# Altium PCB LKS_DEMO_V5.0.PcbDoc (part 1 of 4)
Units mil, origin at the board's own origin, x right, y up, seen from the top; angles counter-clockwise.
Board outline 5414.8 x 3354.56 mil, 2 copper layers (Top Layer, Bottom Layer); 131 components, 85 nets, 355 pads, 272 vias.
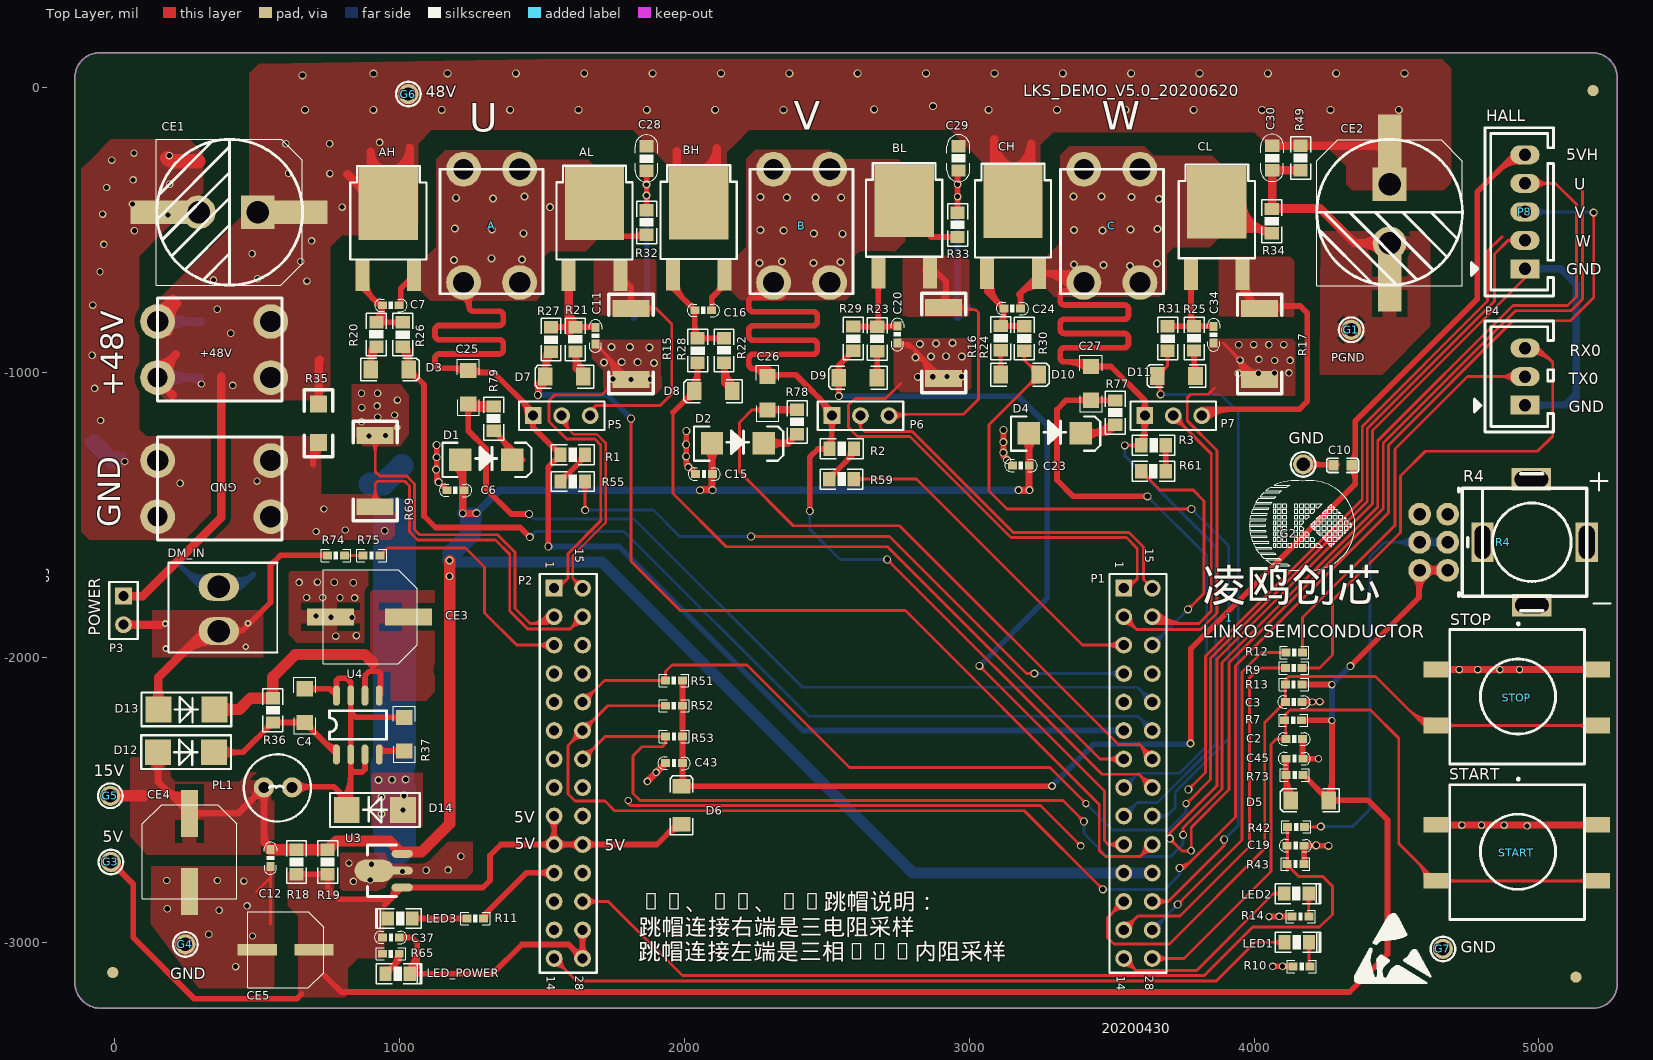
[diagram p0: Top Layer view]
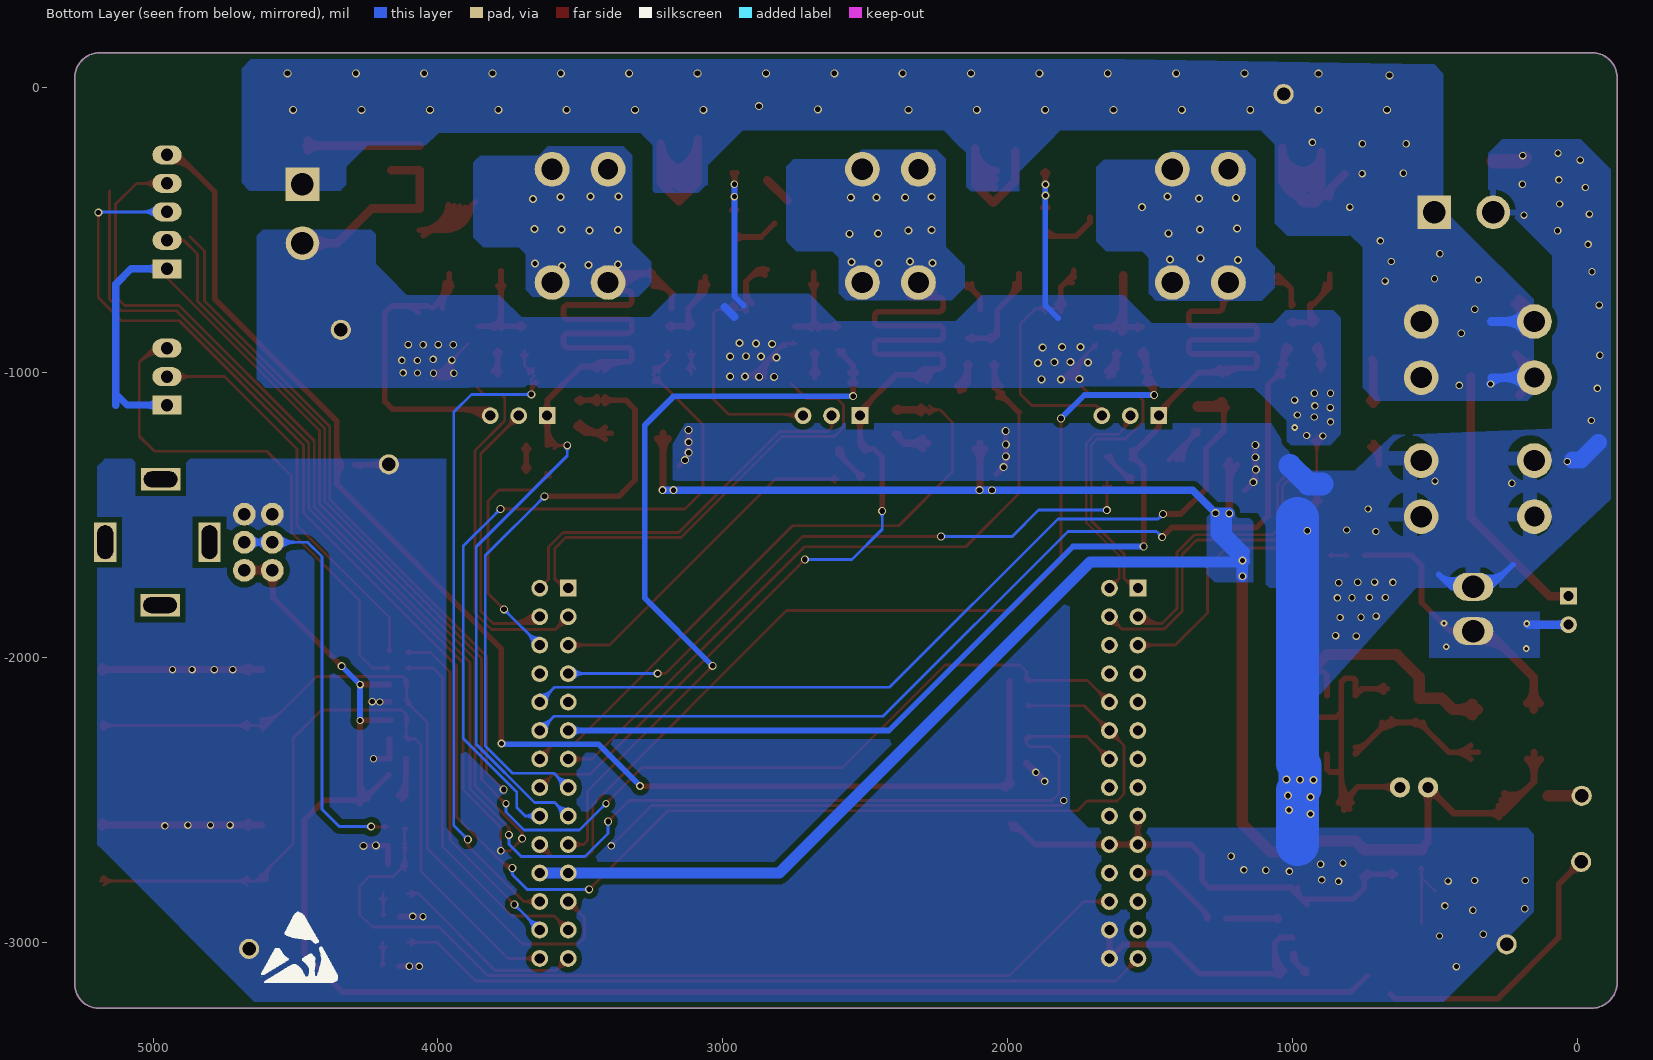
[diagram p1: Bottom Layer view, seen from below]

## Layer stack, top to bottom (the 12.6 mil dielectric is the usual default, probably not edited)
Top Layer: signal copper 1.4
Dielectric: dielectric 12.6, FR-4, Dk 4.8
Bottom Layer: signal copper 1.4

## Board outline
-140.37,-3140.27 ccw(c-48.64,-3140.27) -48.64,-3232 5190.27,-3231.65 ccw(c5190.27,-3147.49) 5274.43,-3147.49 5274.43,35.95 ccw(c5187.82,35.95) 5187.82,122.56 -53.53,122.56 ccw(c-53.53,35.95) -140.14,35.95

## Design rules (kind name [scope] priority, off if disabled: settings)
Clearance [InPolygon] p1: gap=20
Clearance Clearance_48V [InNet('+48V')] p2: gap=30
Clearance Clearance_4 [InNet('PGND')] p3 off: gap=20
Clearance Clearance_5V [InNet('+5V')] p4 off: gap=20
Clearance Clearance_15V [InNet('+15V')] p5: gap=20
Clearance Clearance_5 [All] p6: gap=7.87
ComponentClearance [All] p1 off: gap=0 collisioncheckmode=3 verticalgap=0 showdistances=FALSE
FabricationTestpoint [(IsPad And (OnTopLayer Or OnBottomLayer))] p1: side=3 testpointundercomponent=TRUE minsize=40 maxsize=100 preferedsize=60 minholesize=0 maxholesize=40 preferedholesize=32 testpointgrid=1 allowsidetop=TRUE allowsidebottom=TRUE usegrid=TRUE gridtolerance=0.01
PlaneConnect [All] p1: planeconnectstyle=Direct reliefexpansion=20 reliefentries=4 reliefconductorwidth=10 reliefairgap=10
PolygonConnect [All] p1: connectstyle=Direct reliefconductorwidth=50 reliefentries=4 polygonreliefangle="90 Angle"
RoutingVias [All] p1: holewidth=13.78 width=19.68 viastyle="Through Hole" minholewidth=13.78 minwidth=19.68 maxholewidth=13.78 maxwidth=19.68
SilkscreenOverComponentPads SilkToSolderMaskClearance [IsPad] p1: minsilkscreentomaskgap=10
SolderMaskExpansion [All] p1: expansion=4
Width Width_2 [All] p1 off: maxlimit=10 minlimit=10 preferedwidth=10
Width Width_1 [InNet('5V-T')] p2 off: maxlimit=40 minlimit=40 preferedwidth=40
Width Width_VH [InNet('5V1')] p3 off: maxlimit=40 minlimit=40 preferedwidth=40
Width Width_5V [InNet('5V')] p4 off: maxlimit=40 minlimit=40 preferedwidth=40
Width Width_14.3V [InNet('+14.3V')] p5 off: maxlimit=50 minlimit=50 preferedwidth=50
Width Width_15V [InNet('+15V')] p6 off: maxlimit=40 minlimit=40 preferedwidth=40
Width Width_48V [InNet('+48V')] p7 off: maxlimit=40 minlimit=40 preferedwidth=40
Width [All] p8: maxlimit=200 minlimit=1 preferedwidth=40
24 further rules are at their usual default settings.

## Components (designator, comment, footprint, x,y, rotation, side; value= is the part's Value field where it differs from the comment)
1 "LKS_sign" LKS_LOGO2 3913.31,-1861.12 r0 top
+48V "M4" M4_CONECTOR 587.24,-737.97 r180 top
A "M4" M4_CONECTOR 1503.84,-723.16 r90 top
AH "NCE8295AK" TO-252 960.46,-532.18 r0 top
AL "NCE8295AK" TO-252 1684.09,-531.73 r0 top
B "M4" M4_CONECTOR 2592.15,-723.16 r90 top
BH "NCE8295AK" TO-252 2050.06,-530.17 r0 top
BL "NCE8295AK" TO-252 2771.14,-522.9 r0 top
C "M4" M4_CONECTOR 3681.8,-723.16 r90 top
C2 "100nF/50V" 0603C#1 4170.04,-2286.71 r180 top
C3 "100nF/50V" 0603C#1 4109.35,-2156.04 r0 top
C4 "10uF/100V" 1206#1 666.13,-2227.86 r90 top (schematic designator CF2)
C6 "100nF/50V" 0603C#1 1166.15,-1413.01 r0 top
C7 "10nF/50V" 0603C#1 939.25,-763.4 r0 top
C10 "100nF/50V" 0603C#2 4310.55,-1325.62 r180 top
C11 "10nF/50V" 0603C#1 1687.64,-841.38 r270 top
C12 "100nF/50V" 0603C#1 546.38,-2675.06 r270 top (schematic designator C351)
C15 "100nF/50V" 0603C#1 2039.42,-1355.82 r0 top
C16 "10nF/50V" 0603C#1 2036.35,-781.02 r0 top
C19 "100nF/50V" 0603C#1 4174.8,-2661.32 r180 top
C20 "10nF/50V" 0603C#1 2747.52,-836.3 r270 top
C23 "100nF/50V" 0603C#1 3151.34,-1325.92 r0 top
C24 "10nF/50V" 0603C#1 3121.14,-774.76 r0 top
C25 "10uF/25V" 1206#1 1240.4,-1110.36 r90 top (schematic designator CAH1)
C26 "10uF/25V" 1206#1 2291.34,-1131.27 r90 top (schematic designator CBH1)
C27 "10uF/25V" 1206#1 3426.66,-1096.7 r90 top (schematic designator CCH1)
C28 "100nF/100V" 0805C 1866.99,-290.99 r90 top (schematic designator CA)
C29 "100nF/100V" 0805C 2961.99,-290.67 r90 top (schematic designator CB)
C30 "100nF/100V" 0805C 4063.55,-289.6 r90 top (schematic designator CC)
C34 "10nF/50V" 0603C#1 3857.8,-837.72 r270 top
C37 "100nF/50V" 0603C#1 998.61,-2983.24 r180 top
C43 "100nF/50V" 0603C#1 1933.69,-2371.26 r0 top
C45 "100nF/50V" 0603C#1 4170.76,-2355.72 r180 top
CE1 "220uF/63V" "220UF/25V 12.5*12.5" 503.17,-437.15 r270 top (schematic designator CC3)
CE2 "220uF/63V" "220UF/25V 12.5*12.5" 4475.37,-337.23 r0 top (schematic designator CC1)
CE3 "10UF/100V" "220UF/25V paster8*10" 894.06,-1857.56 r270 top (schematic designator CF1)
CE4 "220uF/25V  8*10" "220UF/25V paster8*10" 262.36,-2684.79 r0 top (schematic designator C391)
CE5 "220uF/16V" "220UF/16V PASTER6.3*7.7 - DUPLICATE" 599.7,-3026.55 r270 top (schematic designator C36)
CH "NCE8295AK" TO-252 3153.33,-524.74 r0 top
CL "NCE8295AK" TO-252 3869.04,-527.35 r0 top
D1 "US1J" SMA金丰 1304.37,-1305.74 r0 top
D2 "US1J" SMA金丰 2187.53,-1248.27 r0 top
D3 "1N4007" D1206#1 898.55,-988.88 r0 top
D4 "US1J" SMA金丰 3300.41,-1213.21 r0 top
D5 "1N4007" D1206#2 4130.39,-2500.13 r0 top
D6 "1N4007" D1206#2 1990.99,-2454.23 r270 top
D7 "1N4007" D1206#1 1645.15,-1014.31 r180 top
D8 "1N4007" D1206#1 2167.67,-1065.43 r180 top
D9 "1N4007" D1206#1 2675.86,-1018.22 r180 top
D10 "1N4007" D1206#1 3110.43,-1007.51 r0 top
D11 "1N4007" D1206#1 3793.99,-1012.14 r180 top
D12 "ES1J" DO-214AC 250.05,-2333.06 r0 top (schematic designator DP1)
D13 "1N4007" DO-214AC 251.5,-2182.97 r0 top (schematic designator DD6)
D14 "ES1J" DO-214AC 912.83,-2535.22 r180 top (schematic designator D02)
DM_IN "CON2" SIP3.96-2 365.35,-1907.97 r90 top
G1 "PAD1.2" PAD1.2 4340.63,-849.76 r0 top
G2 "PAD1.2" PAD1.2 4171.95,-1322.36 r0 top
G3 "PAD1.2" PAD1.2 -13.75,-2718.17 r0 top
G4 "PAD1.2" PAD1.2 247.83,-3007.54 r0 top
G5 "PAD1.2" PAD1.2 -15.81,-2485.75 r0 top
G6 "PAD1.2" PAD1.2 1030.82,-22.05 r0 top (schematic designator G12)
G7 "PAD1.2" PAD1.2 4662.85,-3023.47 r0 top
GND "M4" M4_CONECTOR 587.24,-1226.14 r180 top
LED1 "LED" SOD323 4146.77,-2998.22 r0 top
LED2 "LED" SOD323 4145.98,-2827.12 r0 top
LED3 "LED" SOD323 1003.88,-2918.56 r180 top
LED_POWER "LED_R" SOD323 990.38,-3108.82 r0 top (schematic designator LED)
P1 "Header 14X2A" HDR2X14_CEN 3542.25,-1756.82 r270 top (schematic designator P7)
P2 "Header 14X2A" HDR2X14_CEN 1542.25,-1756.82 r270 top (schematic designator P5)
P3 "Header 2" HDR1X2 30.28,-1784.94 r270 top
P4 "P13" 2.54-XH-3A-180 4950.98,-1114.16 r270 top (schematic designator P13)
P5 "Header 3" HDR1X3 1468.79,-1151.24 r0 top (schematic designator P17)
P6 "Header 3" HDR1X3 2517.75,-1151.24 r0 top (schematic designator P18)
P7 "Header 3" HDR1X3 3616.05,-1151.24 r0 top (schematic designator P19)
P8 "Header 5" 2.54-XH-5A-180 4950.7,-435.64 r270 top (schematic designator P21)
PL1 "330uH" L_DIP_6*8MM 523.71,-2456.42 r0 top
R1 "20K 1%" 0805R 1650.48,-1288.54 r180 top
R2 "20K 1%" 0805R 2594.94,-1267.81 r180 top
R3 "20K 1%" 0805R 3689.51,-1255.52 r180 top
R4 "RPot" RK097-W-1 4874.36,-1595.66 r270 top
R7 "10K" 0603R 4166.32,-2220.83 r180 top
R9 "10R" 0603R 4109.61,-2037.33 r0 top
R10 "1K1%" 0603R 4195.91,-3084.6 r180 top
R11 "1K1%" 0603R 1236.12,-2916.6 r0 top (schematic designator R27)
R12 "10R" 0603R 4170.04,-1982.47 r180 top
R13 "10K" 0603R 4109.35,-2095.34 r0 top
R14 "1K1%" 0603R 4192,-2909.82 r180 top
R15 "0.005R/2512" 2512 1812.75,-776.09 r270 top (schematic designator R301)
R16 "0.005R/2512" 2512 2909.76,-1019.43 r90 top (schematic designator R302)
R17 "0.005R/2512" 2512 4019.41,-776.09 r270 top (schematic designator R303)
R18 "1.5K" 0805R 637.92,-2675.77 r270 top (schematic designator R791)
R19 "1.5K" 0805R 747.07,-2675.77 r270 top (schematic designator R761)
R20 "10R" 0805R 918.27,-823.64 r270 top (schematic designator K+A1)
R21 "10R" 0805R 1616.94,-840.56 r270 top (schematic designator K-A1)
R22 "10R" 0805R 2138.61,-879.87 r270 top (schematic designator K+B1)
R23 "10R" 0805R 2676.33,-839.51 r270 top (schematic designator K-B1)
R24 "10R" 0805R 3110.16,-836.37 r270 top (schematic designator K+C1)
R25 "10R" 0805R 3789.15,-837.14 r270 top (schematic designator K-C1)
R26 "51R" 0805R 1010.51,-909.43 r90 top (schematic designator K1)
R27 "51R" 0805R 1531.29,-926.62 r90 top (schematic designator K2)
R28 "51R" 0805R 2046.11,-965.39 r90 top (schematic designator K3)
R29 "51R" 0805R 2592.71,-923.58 r90 top (schematic designator K4)
R30 "51R" 0805R 3192.94,-922.91 r90 top (schematic designator K5)
R31 "51R" 0805R 3696.16,-923.03 r90 top (schematic designator K6)
R32 "51K" 0805R 1866.99,-429.93 r270 top (schematic designator RA1)
R33 "51K" 0805R 2958.78,-438.57 r270 top (schematic designator RB1)
R34 "51K" 0805R 4061.82,-425.61 r270 top (schematic designator RC1)
R35 "47K/0805" 1206#2 715.63,-1177.64 r270 top (schematic designator RA-5)
R36 "150K" 0805R 554.9,-2228.54 r90 top (schematic designator RP1)
R37 "1R" 1206#1 1016.08,-2328.28 r90 top (schematic designator RP2)
R42 "10K" 0603R 4176.57,-2594.78 r180 top
R43 "20K1%" 0603R 4174.28,-2725.73 r180 top
R49 "51K" 0805R 4162.89,-204.18 r270 top
R51 "2K" 0603R 1933.22,-2081.37 r0 top
R52 "2K" 0603R 1933.48,-2169.52 r0 top
R53 "2K" 0603R 1933.69,-2278.19 r0 top
R55 "20K 1%" 0805R 1650.48,-1382.3 r180 top
R59 "20K 1%" 0805R 2594.28,-1374.16 r180 top
R61 "20K 1%" 0805R 3603.91,-1346.42 r0 top
R65 "3.3K" 0603R 939.57,-3040.48 r0 top
R69 "0.005R/2512" 2512 914.66,-1222.47 r270 top
R73 "10K" 0603R 4171.21,-2412.65 r180 top
R74 "20K1%" 0603R 746.62,-1641.8 r0 top
R75 "20K1%" 0603R 871.84,-1641.8 r0 top
R77 "4.7R" 0805R 3512.15,-1097.85 r270 top
R78 "4.7R" 0805R 2395.27,-1130.53 r270 top
R79 "4.7R" 0805r 1329.96,-1118.93 r270 top
START "SW-PB" "SW-PB  12*12" 4922.12,-2685.6 r0 top
STOP "SW-PB" "SW-PB  12*12" 4922.12,-2140.75 r0 top
U3 "LM7805" SOT-89 959.68,-2748.61 r90 top
U4 "LKS611" so-8 780.21,-2340.28 r90 top

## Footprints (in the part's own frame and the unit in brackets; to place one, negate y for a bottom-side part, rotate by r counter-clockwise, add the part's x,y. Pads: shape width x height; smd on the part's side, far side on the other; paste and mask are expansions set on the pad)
2.54-XH-3A-180 [mm]
  rect 1.7x2.6 hole 1.1: 1(0,0)
  oval 1.7x2.6 hole 1.1: 2(-2.54,0) 3(-5.08,0)
  silkscreen extent -7.49,-4.5 2.41,2.54
2.54-XH-5A-180 [mm]
  rect 1.7x2.6 hole 1.1: 1(5.08,0)
  oval 1.7x2.6 hole 1.1: 2(2.54,0) 3(0,0) 4(-2.54,0) 5(-5.08,0)
  silkscreen extent -7.49,-4.78 7.49,2.54
"220UF/16V PASTER6.3*7.7 - DUPLICATE" [mm]
  rect 1x3.5 smd: 1(0,2.54) 2(0,-2.54)
  silkscreen extent -3.4,-3.4 3.4,3.4
"220UF/25V 12.5*12.5" [mm]
  rect 2.1x5.5 smd: 1(0,3.429)
  rect 3x3 hole 2: 1(0,-0.04)
  round 3 hole 2: 2(0,-5.3)
  rect 2.1x5 smd: 2(0,-8.867)
  silkscreen extent -6.5,-9.07 6.5,3.96
"220UF/25V paster8*10" [mm]
  rect 1.5x4.2 smd: 1(0,3.492) 2(0,-3.492)
  silkscreen extent -4.2,-4.13 4.2,4.27
0603C#1 [mm]
  rect 0.8x0.7 smd: 1(0,0) 2(1.5,0)
  silkscreen extent -0.68,-0.57 2.21,0.55
0603C#2 [mm]
  rect 0.9x0.95 smd: 1(-0.813,0) 2(0.813,0)
  silkscreen extent -1.42,-0.64 1.42,0.64
0603R [mm]
  rect 0.8x0.7 smd: 1(0,0) 2(1.5,0)
  silkscreen extent -0.55,-0.55 2.05,0.55
0805C [mm]
  rect 1.1x1.27 smd: 1(0,0) 2(2.175,0)
  silkscreen extent -1,-1.01 3.2,1.03
0805R [mm]
  rect 1.1x1.27 smd: 1(0,0) 2(2.175,0)
  silkscreen extent -0.81,-0.89 3,0.89
0805r [mm]
  rect 1.1x1.27 smd: 1(0,0) 2(2.175,0)
  silkscreen extent -0.81,-0.89 3,0.89
1206#1 [mm]
  rect 1.35x1.45 smd: 1(-0.01,-0.01) 2(2.99,-0.01)
  silkscreen extent -1.02,-1 4,0.98
1206#2 [mm]
  rect 1.524x1.524 smd: 1(-1.714,0) 2(1.714,0)
  silkscreen extent -2.98,-1.27 2.98,1.27
2512 [mm]
  rect 1.5x3.3 smd: 1(-0.04,-0.01) 2(6.31,-0.01)
  silkscreen extent -1.31,-1.98 7.56,1.96
D1206#1 [mm]
  rect 1.3x1.6 smd: 1(0,0) 2(3.4,0)
  silkscreen extent -0.91,-1.02 4.31,1.02
D1206#2 [mm]
  rect 1.3x1.6 smd: 1(3.346,-0.04) 2(-0.054,-0.04)
  silkscreen extent -0.97,-1.06 4.26,0.98
DO-214AC [mm]
  rect 2.3x2.3 smd: 1(-2.502,0) 2(2.502,0)
  silkscreen extent -4,-1.5 4,1.52
HDR1X2 [mm] "Connector; Header; 2 Position"
  rect 1.5x1.5 hole 0.9: 1(0,0)
  round 1.5 hole 0.9: 2(2.54,0)
  silkscreen extent -1.27,-1.27 3.81,1.27
HDR1X3 [mm]
  rect 1.5x1.5 hole 0.9: 1(0,0)
  round 1.5 hole 0.9: 2(2.54,0) 3(5.08,0)
  silkscreen extent -1.27,-1.27 6.35,1.27
HDR2X14_CEN [mm] "Connector; Header; 14x2 Position"
  rect 1.5x1.5 hole 0.9: 1(0,0)
  round 1.5 hole 0.9: 2(2.54,0) 3(5.08,0) 4(7.62,0) 5(10.16,0) 6(12.7,0) 7(15.24,0) 8(17.78,0) 9(20.32,0) 10(22.86,0) 11(25.4,0) 12(27.94,0) 13(30.48,0) 14(33.02,0) 15(0,2.54) 16(2.54,2.54) 17(5.08,2.54) 18(7.62,2.54) 19(10.16,2.54) 20(12.7,2.54) 21(15.24,2.54) 22(17.78,2.54) 23(20.32,2.54) 24(22.86,2.54) 25(25.4,2.54) 26(27.94,2.54) 27(30.48,2.54) 28(33.02,2.54)
  silkscreen extent -1.27,-1.27 34.29,3.81
L_DIP_6*8MM [mm]
  round 1.8 hole 1: 1(0,0) 2(2.5,0)
  silkscreen extent -1.8,-3.04 4.2,2.96
LKS_LOGO2 [mil]
  silkscreen extent 70,167 440,482
M4_CONECTOR [mm]
  round 3.1 hole 1.9: 1(1,7.1) 1(1,2.1) 1(11.1,2.1)
  round 3.1 hole 1.8: 1(11.1,7.1)
  silkscreen extent 0,0 11.1,9.2
PAD1.2 [mm]
  round 1.8 hole 1.2: 1(0,0)
  silkscreen extent -1.1,-1.1 1.1,1.1
RK097-W-1 [mm] "电位器-"
  rect 2x3.5 hole 1.4 slot 3 at 90 deg: 0(-5.613,2.503) 0(5.613,2.554)
  rect 3.5x2 hole 1.4 slot 3 at 0 deg: 0(0,7.45) 0(0,-1.85)
  round 2.032 hole 1.1: 1(2.5,-7.45) 2(-2.5,-7.45) 3(0,-7.45) 4(-2.5,-4.95) 5(0,-4.95) 6(2.5,-4.95)
  silkscreen extent -6.1,-3.95 6.1,7.45
SIP3.96-2 [mm]
  oval 2.5x3.6 hole 2: 1(0,0) 2(3.96,0)
  silkscreen extent -1.91,-5.21 6.1,4.5
SMA金丰 [mm]
  rect 2x2 smd: 1(-2.312,0) 2(2.313,0)
  silkscreen extent -3.91,-1.55 4.04,1.5
so-8 [mm]
  oval 1.8x0.61 smd: 1(-0.02,0.05) 2(-0.02,-1.22) 3(-0.02,-2.49) 4(-0.02,-3.76) 5(5.238,-3.76) 6(5.238,-2.49) 7(5.238,-1.22) 8(5.238,0.05)
  silkscreen extent 1.35,-4.4 3.89,0.68
SOD323 [mil]
  rect 43.31x50 smd: 1(-40,-2) 2(45.63,-2)
  silkscreen extent -72,-37 87,33
SOT-89 [mm]
  oval 0.7x1.9 smd: 1(-1.5,-1.25) 3(1.5,-1.25)
  oval 2x3.5 smd: 2(0,1.25)
  oval 0.7x2.1 smd: 2(0,-1.15)
  silkscreen extent -2.3,-0.75 2.3,1.85
"SW-PB  12*12" [mm]
  rect 2.2x1.397 smd: 1(-7.2,2.5) 2(-7.2,-2.5) 3(7.2,2.5) 4(7.2,-2.5)
  silkscreen extent -5.98,-5.94 6.02,6.68
TO-252 [mm]
  rect 1.25x2.85 smd: 1(-2.3,-3.2) 3(2.3,-3.2)
  rect 5.3x6.5 smd: 2(0,3.2)
  silkscreen extent -3.4,-1.8 3.4,6.55

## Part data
A B C: library part Socket, "Socket"
C4: library part Cap, "Capacitor"
CE1 CE3: library part CD, "Electrolytic Capacitor"
CE2: library part "Cap Pol1", "Polarized Capacitor (Radial)"
D3 D7 D8 D9 D10 D11: library part Diode, "Default Diode"
D5 D6: library part "Diode 1N4007", "1 Amp General Purpose Rectifier"
D12 D13 D14: library part D, "Diode"
DM_IN: "Connector"
G1 G2 G3 G4 G5 G6 G7: library part CON1, "Connector"
LED_POWER: library part LED
P1: "Header, 14-Pin, Dual row"
P3: "Header, 2-Pin"
P8: "Header, 5-Pin"
PL1: library part L
R1 R2 R3: library part RES/1
R4: "Potentiometer"
R11 R36 R37: library part Res2, "Resistor"
R18 R19: library part R-2W, "1W或2W?"
R20 R21 R22 R23 R24 R25 R26 R27 R28 R29 R30 R31: library part Res1, "Resistor"
R35 R42 R43 R74 R75: library part R
R69: library part RES2?
R79: library part RES2短
START STOP: "Switch"

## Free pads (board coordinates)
  round 39.37 / inner round 0 / far side round 0 all layers, no hole: 1(-7.22,-3106.07) 3(5189.97,-9.89) 4(5129.69,-3122.48)

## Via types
v1: diameter 26, hole 18, Top Layer to Bottom Layer, 117 vias
v2: diameter 28, hole 20, Top Layer to Bottom Layer, 77 vias
v3: diameter 28, hole 18, Top Layer to Bottom Layer, 73 vias
v4: diameter 23.62, hole 11.81, Top Layer to Bottom Layer, 5 vias

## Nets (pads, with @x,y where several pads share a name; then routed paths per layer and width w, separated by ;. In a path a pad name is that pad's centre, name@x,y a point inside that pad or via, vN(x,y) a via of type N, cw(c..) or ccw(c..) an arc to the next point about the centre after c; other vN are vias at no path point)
5V-T: C45.2 D5.2 R73.2 | length 344.8
  Top Layer w20: R73.2@4111.7,-2412.19 C45.2@4111.7,-2355.72 ; D5.2@4112.15,-2485.74 R73.2@4112.15,-2412.65 ; 4112.15,-2467.56 ccw(c4156.51,-2467.56) 4125.15,-2498.92 cw(c4156.51,-2467.56) 4112.15,-2467.56 ; R73.2@4112.15,-2419.27 ccw(c4204.79,-2419.27) 4139.29,-2484.78 cw(c4204.79,-2419.27) R73.2@4112.15,-2419.27
5VH: C10.1 C43.2 D6.2 P8.5 R51.2 R52.2 R53.2 | length 5492.9
  Top Layer w20: D6.2@1989.42,-2452.1 v3@3289.67,-2452.1 ; R52.2@1992.54,-2169.52 R52.2@1992.75,-2169.52 ; D6.2@1992.75,-2448.77 R51.2@1992.75,-2081.84 ; v3@3777.74,-2302.94 3777.74,-1968.54 4354.39,-1391.89 4354.39,-1170.91 4782.69,-742.6 4782.69,-366.17 4913.23,-235.64 P8.5@4950.7,-235.64 ; D6.2@2006.35,-2441.08 ccw(c2032.96,-2414.46) 2032.96,-2452.1 ; D6.2@2006.35,-2441.08 cw(c2039.18,-2408.25) 1992.75,-2408.25 ccw(c2039.18,-2408.25) D6.2@2006.35,-2441.08 ; D6.2@2006.35,-2441.08 ccw(c2032.96,-2414.46) 2032.96,-2452.1 ; 2032.96,-2452.1 ccw(c2032.96,-2489.74) 2006.35,-2463.13 cw(c2032.96,-2489.74) 2032.96,-2452.1 ; D6.2@1984.3,-2441.08 ccw(c1963.9,-2420.68) 1992.75,-2420.68 cw(c1963.9,-2420.68) D6.2@1984.3,-2441.08 ; C10.1@4337.09,-1332.06 cw(c4295.34,-1373.81) 4354.39,-1373.81 ccw(c4295.34,-1373.81) C10.1@4337.09,-1332.06 ; C10.1@4337.09,-1319.18 ccw(c4295.34,-1277.43) 4354.39,-1277.43 cw(c4295.34,-1277.43) C10.1@4337.09,-1319.18 ; 4859.2,-289.66 cw(c4932.98,-363.44) 4932.98,-259.1 ccw(c4932.98,-363.44) 4859.2,-289.66 ; 4893.34,-255.52 cw(c4932.98,-295.16) 4932.98,-239.1 ccw(c4932.98,-295.16) 4893.34,-255.52
  Bottom Layer w20: v3(3289.67,-2451.14) 3435.89,-2304.92 3774.41,-2304.92 v3(3776.77,-2302.56) ; 3761.41,-2304.92 ccw(c3761.41,-2287.2) 3773.94,-2299.73 cw(c3761.41,-2287.2) 3761.41,-2304.92
+5V: C37.2 CE5.1 D5.1 D6.1 G3.1 LED3.2 P2.9 P2.10 P2.24 R4.1 R4.6 R7.1 R13.2 R18.2 R19.2 R65.1 R73.1 U3.1 | length 11175.9
  Top Layer w20: G3.1@-13.75,-2718.17 64.46,-2796.38 64.46,-2983.74 279.1,-3198.38 639.24,-3198.38 655.62,-3181.99 ; R18.2@637.92,-2761.01 747.07,-2761.01 747.07,-2809.07 787,-2849 967.55,-2849 ; 738.26,-3117.97 794.75,-3174.47 4335.11,-3174.47 4467.98,-3041.6 4467.98,-2569.96 4399.74,-2501.71 D5.1@4262.12,-2501.71 ; 947.87,-2868.69 U3.1@1008.89,-2807.66 1292.23,-2807.66 1317,-2782.89 1317,-2695.27 1355.46,-2656.82 P2.10@1542.25,-2656.82 ; P2.9@1542.25,-2556.82 P2.10@1542.25,-2656.82 ; D6.1@1989.42,-2585.96 1973.94,-2585.96 1903.08,-2656.82 P2.24@1642.25,-2656.82 P2.10@1542.25,-2656.82 ; R7.1@4166.32,-2220.83 v1@4272.99,-2220.83 ; R13.2@4168.4,-2095.34 v1(4273,-2095.35) ; R73.1@4171.21,-2412.65 4172.92,-2412.65 D5.1@4262.02,-2501.75 ; D5.1@4272.99,-2490.84 v1(4272.99,-2221.42) ; v2(4337.69,-2030.68) 4578.6,-1789.77 4578.6,-1692.52 R4.6@4677.02,-1692.52 ; 29.67,-2761.58 ccw(c-13.75,-2805) -13.75,-2743.6 cw(c-13.75,-2805) 29.67,-2761.58 ; 29.67,-2761.58 cw(c73.08,-2718.17) 11.68,-2718.17 ccw(c73.08,-2718.17) 29.67,-2761.58 ; 747.07,-2789.53 ccw(c718.94,-2789.53) 738.83,-2769.64 cw(c718.94,-2789.53) 747.07,-2789.53 ; 747.07,-2789.53 cw(c775.21,-2789.53) 755.32,-2769.64 ccw(c775.21,-2789.53) 747.07,-2789.53 ; 1495.11,-2656.82 ccw(c1495.11,-2609.67) P2.10@1528.44,-2643.01 ; 1495.11,-2656.82 cw(c1495.11,-2703.96) 1528.44,-2670.62 ccw(c1495.11,-2703.96) 1495.11,-2656.82 ; 1495.11,-2656.82 ccw(c1495.11,-2609.67) P2.10@1528.44,-2643.01 ; P2.10@1528.44,-2643.01 ccw(c1495.11,-2609.67) 1542.25,-2609.67 ; P2.10@1528.44,-2643.01 ccw(c1495.11,-2609.67) 1542.25,-2609.67 ; 1542.25,-2609.67 ccw(c1589.39,-2609.67) P2.10@1556.06,-2643.01 ; 1542.25,-2609.67 ccw(c1589.39,-2609.67) P2.10@1556.06,-2643.01 ; 1542.25,-2603.96 ccw(c1495.11,-2603.96) 1528.44,-2570.62 cw(c1495.11,-2603.96) 1542.25,-2603.96 ; 1542.25,-2603.96 cw(c1589.39,-2603.96) 1556.06,-2570.62 ccw(c1589.39,-2603.96) 1542.25,-2603.96 ; P2.10@1556.06,-2643.01 ccw(c1589.39,-2609.67) 1589.39,-2656.82 ; P2.10@1556.06,-2643.01 ccw(c1589.39,-2609.67) 1589.39,-2656.82 ; 1589.39,-2656.82 ccw(c1589.39,-2703.96) 1556.06,-2670.62 cw(c1589.39,-2703.96) 1589.39,-2656.82 ; 1595.11,-2656.82 ccw(c1595.11,-2609.67) 1628.44,-2643.01 cw(c1595.11,-2609.67) 1595.11,-2656.82 ; 1595.11,-2656.82 cw(c1595.11,-2703.96) 1628.44,-2670.62 ccw(c1595.11,-2703.96) 1595.11,-2656.82 ; 1689.39,-2656.82 ccw(c1689.39,-2703.96) 1656.06,-2670.62 cw(c1689.39,-2703.96) 1689.39,-2656.82 ; 1689.39,-2656.82 cw(c1689.39,-2609.67) 1656.06,-2643.01 ccw(c1689.39,-2609.67) 1689.39,-2656.82 ; 4299.76,-2501.71 ccw(c4299.76,-2539.35) 4273.15,-2512.73 cw(c4299.76,-2539.35) 4299.76,-2501.71 ; 4299.76,-2501.71 cw(c4299.76,-2464.07) 4273.15,-2490.69 ccw(c4299.76,-2464.07) 4299.76,-2501.71 ; R4.1@4602.27,-1715.3 cw(c4657.26,-1770.29) 4657.26,-1692.52 ccw(c4657.26,-1770.29) R4.1@4602.27,-1715.3 ; R4.1@4602.27,-1715.3 ccw(c4659.41,-1772.44) 4578.6,-1772.44 cw(c4659.41,-1772.44) R4.1@4602.27,-1715.3 ; R18.2@649.51,-2769.64 cw(c670.34,-2790.47) 670.34,-2761.01 ccw(c670.34,-2790.47) R18.2@649.51,-2769.64 ; R18.2@649.51,-2753.16 ccw(c668.47,-2734.2) 668.47,-2761.01 cw(c668.47,-2734.2) R18.2@649.51,-2753.16 ; 714.66,-2761.01 cw(c714.66,-2790.47) 735.49,-2769.64 ccw(c714.66,-2790.47) 714.66,-2761.01 ; 716.53,-2761.01 ccw(c716.53,-2734.2) 735.49,-2753.16 cw(c716.53,-2734.2) 716.53,-2761.01 ; 962.11,-2854.44 ccw(c915.34,-2807.66) 981.49,-2807.66 cw(c915.34,-2807.66) 962.11,-2854.44 ; U3.1@996.26,-2820.3 ccw(c983.62,-2807.66) 1001.49,-2807.66 cw(c983.62,-2807.66) U3.1@996.26,-2820.3 ; 1940.55,-2619.35 cw(c1983.51,-2662.31) 1983.51,-2601.55 ccw(c1983.51,-2662.31) 1940.55,-2619.35 ; 4225.18,-2464.91 ccw(c4262.12,-2427.97) 4262.12,-2480.21 cw(c4262.12,-2427.97) 4225.18,-2464.91 ; D5.1@4239.78,-2479.51 cw(c4223.49,-2495.8) 4246.53,-2495.8 ccw(c4223.49,-2495.8) D5.1@4239.78,-2479.51 ; D5.1@4251.1,-2484.78 ccw(c4198.25,-2431.93) 4272.99,-2431.93 cw(c4198.25,-2431.93) D5.1@4251.1,-2484.78 ; R4.1@4559.84,-1715.3 cw(c4514.56,-1760.58) 4578.6,-1760.58 ccw(c4514.56,-1760.58) R4.1@4559.84,-1715.3 ; R4.1@4602.27,-1672.87 ccw(c4649.7,-1625.44) 4649.7,-1692.52 cw(c4649.7,-1625.44) R4.1@4602.27,-1672.87 ; R4.1@4603.27,-1692.52 cw(c4603.27,-1770.29) 4658.27,-1715.3 ccw(c4603.27,-1770.29) R4.1@4603.27,-1692.52 ; R4.1@4610.84,-1692.52 ccw(c4610.84,-1625.44) 4658.27,-1672.87 cw(c4610.84,-1625.44) R4.1@4610.84,-1692.52
  Bottom Layer w20: v1(4272.99,-2221.42) v1(4273,-2095.35) v2@4337.68,-2030.67
+15V: C6.2 C12.1 C15.2 C23.2 CE4.1 D1.1 D2.1 D4.1 D12.1 G5.1 P1.11 P1.25 PL1.1 R18.1 R19.1 U3.3 | length 10742.6
  Top Layer w24: D12.1@151.55,-2333.06 151.55,-2436.48 CE4.1@262.36,-2547.29 432.84,-2547.29 PL1.1@523.71,-2456.42 523.71,-2652.39 C12.1@546.38,-2675.06 ; 151.55,-2413.4 ccw(c71.22,-2413.4) 128.02,-2356.59 cw(c71.22,-2413.4) 151.55,-2413.4 ; 151.55,-2413.4 cw(c231.89,-2413.4) 175.08,-2356.59 ccw(c231.89,-2413.4) 151.55,-2413.4 ; 304.68,-2547.29 ccw(c304.68,-2589.61) 274.76,-2559.69 cw(c304.68,-2589.61) 304.68,-2547.29 ; 304.68,-2547.29 cw(c304.68,-2504.98) 274.76,-2534.9 ccw(c304.68,-2504.98) 304.68,-2547.29 ; 483.7,-2496.43 ccw(c443.7,-2456.42) 500.27,-2456.42 cw(c443.7,-2456.42) 483.7,-2496.43 ; 483.7,-2496.43 cw(c523.71,-2536.43) 523.71,-2479.86 ccw(c523.71,-2536.43) 483.7,-2496.43 ; 523.71,-2513 ccw(c467.13,-2513) 507.14,-2472.99 cw(c467.13,-2513) 523.71,-2513 ; 523.71,-2513 cw(c580.28,-2513) 540.28,-2472.99 ccw(c580.28,-2513) 523.71,-2513 ; 178.13,-2463.06 ccw(c227.88,-2413.31) 255.48,-2478.02 cw(c227.88,-2413.31) 178.13,-2463.06 ; 203.24,-2488.17 ccw(c242.89,-2448.51) 264.9,-2500.1 cw(c242.89,-2448.51) 203.24,-2488.17 ; 228.35,-2513.28 ccw(c257.91,-2483.71) 274.32,-2522.17 cw(c257.91,-2483.71) 228.35,-2513.28 ; CE4.1@253.46,-2538.39 ccw(c272.93,-2518.91) 283.74,-2544.25 cw(c272.93,-2518.91) CE4.1@253.46,-2538.39 ; 523.71,-2614.06 ccw(c605.41,-2614.06) 547.63,-2671.84 cw(c605.41,-2614.06) 523.71,-2614.06
  Top Layer w25: D1.1@1221.52,-1309.14 v2(1221.52,-1494.22) v2@1269.2,-1494.22 ; v2@2056.97,-1410.97 2096.49,-1410.97 D2.1@2096.49,-1248.27 ; v3@3174.44,-1412.97 v3(3211.77,-1412.97) ; v3@3209.37,-1410.57 D4.1@3209.37,-1213.21 ; 2096.49,-1313.15 ccw(c2031.62,-1313.15) 2077.49,-1267.28 cw(c2031.62,-1313.15) 2096.49,-1313.15 ; 2096.49,-1313.15 cw(c2161.36,-1313.15) 2115.49,-1267.28 ccw(c2161.36,-1313.15) 2096.49,-1313.15 ; 3209.37,-1278.08 ccw(c3144.5,-1278.08) 3190.37,-1232.21 cw(c3144.5,-1278.08) 3209.37,-1278.08 ; 3209.37,-1278.08 cw(c3274.24,-1278.08) 3228.37,-1232.21 ccw(c3274.24,-1278.08) 3209.37,-1278.08 ; D1.1@1194.32,-1324.74 cw(c1128.65,-1390.41) 1221.52,-1390.41 ccw(c1128.65,-1390.41) D1.1@1194.32,-1324.74 ; 1221.52,-1350.81 cw(c1258.39,-1350.81) 1232.32,-1324.74 ccw(c1258.39,-1350.81) 1221.52,-1350.81
  Top Layer w40: G5.1@-15.81,-2485.75 101.69,-2485.75 ; C12.1@546.38,-2675.06 747.78,-2675.06 778.17,-2644.67 964.01,-2644.67 U3.3@1002.59,-2683.25 ; U3.3@1008.89,-2683.25 1076.61,-2683.25 1175.42,-2584.44 v3(1175.42,-1715.06) v3(1175.42,-1660.38) ; 21.45,-2485.75 ccw(c21.45,-2523.01) -4.9,-2496.66 cw(c21.45,-2523.01) 21.45,-2485.75 ; 21.45,-2485.75 cw(c21.45,-2448.49) -4.9,-2474.83 ccw(c21.45,-2448.49) 21.45,-2485.75
  Bottom Layer w25: v2@1267.98,-1494.38 1268.75,-1493.61 1349.38,-1412.97 v2@2098.49,-1412.97 ; v2@2099.02,-1412.97 v3(3173.01,-1412.97) v3(3211.77,-1412.97)
  Bottom Layer w40: 1169.05,-1629.92 1232.41,-1566.57 v2@1232.41,-1493.61 ; v3@1175.42,-1715.43 v3(1175.42,-1715.06) v3(1175.42,-1660.38) ; v2@1222.13,-1493.61 v2@1232.41,-1493.61 ; v2@1267.98,-1494.38 1267.98,-1567.82 v3(1175.42,-1660.38) ; v2(1269.81,-1493.61) 1268.75,-1493.61 v2@1232.41,-1493.61 ; P1.25@3646.78,-2756.94 2801.47,-2756.94 1709.43,-1664.9 1179.93,-1664.9 v3(1175.42,-1660.38) ; v3@1169.42,-1660.38 cw(c1243.82,-1660.38) 1191.21,-1607.77 ccw(c1243.82,-1660.38) v3@1169.42,-1660.38
  other v2: 2054.78,-1413.16 2098.49,-1412.98
+48V: +48V.1 AH.2 BH.2 C28.2 C29.2 C30.2 CE1.1 CE2.1 CH.2 G6.1 P3.1 R35.1 R49.1 | length 9894.8
  Top Layer w30: P3.1@29.39,-1790.6 35.05,-1784.94 97.39,-1784.94 372.99,-1509.34 372.99,-1013.53 ; +48V.1@187.72,-858.14 +48V.1@150.23,-820.65 ; 202.6,-1078.64 150.23,-1026.28 +48V.1@150.23,-1017.5 150.23,-999.63 214.44,-935.42 ; R35.1@715.63,-1110.14 715.63,-958.58 718.88,-955.33 ; 816.85,-303.92 919.12,-406.19 AH.2@960.46,-406.19 ; 1972.11,-223.34 1972.11,-326.23 BH.2@2050.06,-404.19 2113.48,-340.78 2113.48,-211.72 ; C30.2@4063.55,-203.97 CE2.1@4462.56,-203.97 ; 65.35,-1784.94 ccw(c65.35,-1820.01) 40.55,-1795.21 cw(c65.35,-1820.01) 65.35,-1784.94 ; 65.35,-1784.94 cw(c65.35,-1749.87) 40.55,-1774.67 ccw(c65.35,-1749.87) 65.35,-1784.94 ; +48V.1@150.23,-820.65 155.6,-820.65 218.58,-757.67 ; +48V.1@150.23,-820.65 150.23,-794.07 203.63,-740.68 ; 203.62,-740.68 ccw(c242.5,-779.56) 192.27,-801.92 cw(c242.5,-779.56) 203.62,-740.68 ; 214.44,-935.42 ccw(c267.13,-988.11) 194.87,-1006.28 cw(c267.13,-988.11) 214.44,-935.42 ; 218.57,-757.67 ccw(c273.15,-812.25) 196.15,-817.51 cw(c273.15,-812.25) 218.57,-757.67 ; 218.57,-757.67 cw(c172.31,-711.41) 159.35,-775.54 ccw(c172.31,-711.41) 218.57,-757.67 ; 715.63,-1073.93 ccw(c751.85,-1073.93) 726.24,-1099.54 cw(c751.85,-1073.93) 715.63,-1073.93 ; 715.64,-1073.93 cw(c679.42,-1073.93) 705.03,-1099.54 ccw(c679.42,-1073.93) 715.64,-1073.93 ; 898.31,-224.34 ccw(c967.36,-224.34) 964.35,-293.32 cw(c967.36,-224.34) 898.31,-224.34 ; 898.31,-224.33 898.31,-344.04 AH.2@960.46,-406.19 ; AH.2@960.46,-406.19 1035.9,-330.75 1035.9,-210.76 ; 1035.9,-210.76 cw(c953.27,-210.76) 956.73,-293.32 ccw(c953.27,-210.76) 1035.9,-210.76 ; 2113.48,-211.73 cw(c2033.12,-211.73) 2041.14,-291.68 ccw(c2033.12,-211.73) 2113.48,-211.73 ; 3087.56,-181.79 ccw(c3196.29,-181.79) 3172.71,-287.93 cw(c3196.29,-181.79) 3087.56,-181.79 ; 3087.56,-181.78 3087.56,-332.99 CH.2@3153.33,-398.76 3216.82,-335.26 3216.82,-195.96 ; 3216.82,-195.97 cw(c3124.72,-195.97) 3139.24,-286.92 ccw(c3124.72,-195.97) 3216.82,-195.97 ; +48V.1@150.23,-971.47 ccw(c150.23,-903.49) 198.3,-951.56 cw(c150.23,-903.49) +48V.1@150.23,-971.47 ; +48V.1@150.23,-774.62 ccw(c150.23,-727.67) 183.43,-760.87 cw(c150.23,-727.67) +48V.1@150.23,-774.62 ; 853.9,-340.97 cw(c812.3,-382.57) 871.13,-382.57 ccw(c812.3,-382.57) 853.9,-340.97 ; AH.2@898.31,-287.01 ccw(c964.63,-287.01) 961.74,-353.27 cw(c964.63,-287.01) AH.2@898.31,-287.01 ; 898.31,-255.67 ccw(c965.99,-255.67) 963.05,-323.3 cw(c965.99,-255.67) 898.31,-255.67 ; AH.2@957.98,-323.29 ccw(c954.58,-242.04) 1035.9,-242.04 cw(c954.58,-242.04) AH.2@957.98,-323.29 ; AH.2@959.24,-353.26 ccw(c955.89,-273.32) 1035.9,-273.32 cw(c955.89,-273.32) AH.2@959.24,-353.26 ; AH.2@960.49,-383.24 ccw(c957.2,-304.61) 1035.9,-304.61 cw(c957.2,-304.61) AH.2@960.49,-383.24 ; BH.2@2044.14,-321.53 ccw(c2036.45,-244.89) 2113.48,-244.89 cw(c2036.45,-244.89) BH.2@2044.14,-321.53 ; BH.2@2047.14,-351.38 ccw(c2039.78,-278.05) 2113.48,-278.05 cw(c2039.78,-278.05) BH.2@2047.14,-351.38 ; CH.2@3087.56,-293.98 ccw(c3171.36,-293.98) 3153.19,-375.79 cw(c3171.36,-293.98) CH.2@3087.56,-293.98 ; 3087.56,-256.58 ccw(c3179.67,-256.58) 3159.69,-346.5 cw(c3179.67,-256.58) 3087.56,-256.58 ; 3087.56,-219.19 ccw(c3187.98,-219.19) 3166.2,-317.21 cw(c3187.98,-219.19) 3087.56,-219.19 ; CH.2@3143.97,-316.54 ccw(c3130.33,-231.14) 3216.82,-231.14 cw(c3130.33,-231.14) CH.2@3143.97,-316.54 ; CH.2@3148.7,-346.17 ccw(c3135.95,-266.31) 3216.82,-266.31 cw(c3135.95,-266.31) CH.2@3148.7,-346.17 ; 4407.6,-203.97 ccw(c4407.6,-134.46) 4456.75,-183.61 cw(c4407.6,-134.46) 4407.6,-203.97 ; 4415.98,-203.97 cw(c4415.98,-261.63) 4456.75,-220.86 ccw(c4415.98,-261.63) 4415.98,-203.97
  Bottom Layer w30: +48V.1@150.23,-1017.5 299.05,-1017.5 ; +48V.1@150.23,-820.65 301.98,-820.65 ; 261.34,-1017.5 ccw(c261.34,-1128.61) 182.77,-1050.04 cw(c261.34,-1128.61) 261.34,-1017.5 ; 261.34,-1017.5 cw(c261.34,-906.39) 182.77,-984.95 ccw(c261.34,-906.39) 261.34,-1017.5 ; 261.34,-820.65 ccw(c261.34,-931.76) 182.77,-853.19 cw(c261.34,-931.76) 261.34,-820.65 ; 261.34,-820.65 cw(c261.34,-709.54) 182.77,-788.1 ccw(c261.34,-709.54) 261.34,-820.65 ; 253.79,-1017.5 cw(c253.79,-1090.14) 305.15,-1038.77 ccw(c253.79,-1090.14) 253.79,-1017.5
  other v1: 414.21,-1044.94 303.74,-1040.19 407.08,-862.01 359.57,-777.67 674.35,-679.08 346.5,-674.33 500.92,-670.76 652.97,-610.18 481.91,-582.86 690.98,-537.72 797.88,-418.94 755.12,-301.34 610.2,-300.15 600.71,-196.8 753.93,-196.81 929.74,-192.06
  other v2: 667.79,-77.65 907.79,-77.65 1147.79,-77.65 1387.79,-77.65 1627.79,-77.65 1867.79,-77.65 2107.79,-77.65 2347.79,-77.65 3067.79,-77.65 3307.79,-77.65 3547.79,-77.65 3787.79,-77.65 4027.79,-77.65 4267.79,-77.65 4507.79,-77.65 2665.96,-75.9 2872.48,-64.5 658.82,43.38 908.23,49.24 1168.05,50.46 1408.05,50.46 1648.05,50.46 1888.05,50.46 2128.05,50.46 2368.05,50.46 2608.05,50.46 2848.05,50.46 3088.05,50.46 3328.05,50.46 3568.05,50.46 3808.05,50.46 4048.05,50.46 4288.05,50.46 4528.05,50.46
AI: AL.3 P5.3 R15.1 | length 1507.7
  Top Layer w10: P5.3@1667.29,-1137.04 1688.86,-1115.47 ; R15.1@1812.75,-774.75 1900.89,-774.75 ; 1688.86,-1115.47 ccw(c1699.58,-1126.19) 1687.82,-1135.76 cw(c1699.58,-1126.19) 1688.86,-1115.47 ; 1688.86,-1115.47 1915.17,-1115.47 1955.26,-1075.38 1955.26,-829.12 1900.89,-774.75 ; 1900.88,-774.75 ccw(c1900.88,-820.38) 1866.35,-790.55 cw(c1900.88,-820.38) 1900.88,-774.75 ; 1900.88,-774.75 cw(c1900.88,-729.97) 1866.58,-758.75 ccw(c1900.88,-729.97) 1900.88,-774.75 ; P5.3@1668.79,-1126.71 ccw(c1668.79,-1105.39) 1683.86,-1120.46 cw(c1668.79,-1105.39) P5.3@1668.79,-1126.71 ; P5.3@1680.06,-1142.07 cw(c1690.94,-1133.22) 1681.02,-1123.31 ccw(c1690.94,-1133.22) P5.3@1680.06,-1142.07 ; R15.1@1858.78,-784.01 cw(c1879.03,-801.5) 1879.03,-774.75 ccw(c1879.03,-801.5) R15.1@1858.78,-784.01 ; R15.1@1858.92,-765.18 ccw(c1879.44,-747.96) 1879.44,-774.75 cw(c1879.44,-747.96) R15.1@1858.92,-765.18
  Top Layer w20: AL.3@1767.23,-641.42 1767.23,-653.96 1812.75,-699.47 R15.1@1812.75,-785.32 ; AL.3@1765.98,-665.34 cw(c1771.27,-679.93) 1782.24,-668.96 ccw(c1771.27,-679.93) AL.3@1765.98,-665.34 ; AL.3@1772.8,-684.14 cw(c1783.1,-712.53) 1804.46,-691.18 ccw(c1783.1,-712.53) AL.3@1772.8,-684.14 ; R15.1@1798.55,-760.71 ccw(c1764.26,-726.42) 1812.75,-726.42 cw(c1764.26,-726.42) R15.1@1798.55,-760.71 ; 1812.75,-728.33 ccw(c1858.55,-728.33) 1826.17,-760.71 cw(c1858.55,-728.33) 1812.75,-728.33
AP: P2.15 P5.2 | length 1322.9
  Top Layer w8: P5.2@1567.29,-1137.04 1567.29,-1173.14 1610.43,-1216.27 1692.55,-1216.27 1723.11,-1246.83 1723.11,-1527.41 1607.69,-1642.83 1607.69,-1722.25 ; P2.15@1642.25,-1756.82 1607.69,-1722.25 ; 1607.69,-1722.26 ccw(c1631.75,-1698.19) 1637.75,-1731.69 cw(c1631.75,-1698.19) 1607.69,-1722.26 ; 1607.69,-1722.26 cw(c1583.63,-1746.32) 1617.12,-1752.32 ccw(c1583.63,-1746.32) 1607.69,-1722.26 ; 1618.52,-1733.09 ccw(c1635.04,-1716.57) 1639.16,-1739.56 cw(c1635.04,-1716.57) 1618.52,-1733.09 ; 1618.52,-1733.09 cw(c1602,-1749.61) 1625,-1753.73 ccw(c1602,-1749.61) 1618.52,-1733.09 ; P5.2@1570.16,-1151.91 ccw(c1592.8,-1162.99) 1574.98,-1180.82 cw(c1592.8,-1162.99) P5.2@1570.16,-1151.91 ; P5.2@1577.34,-1155.43 ccw(c1603.43,-1168.2) 1582.89,-1188.74 cw(c1603.43,-1168.2) P5.2@1577.34,-1155.43 ; P5.2@1584.53,-1158.94 ccw(c1614.06,-1173.4) 1590.81,-1196.66 cw(c1614.06,-1173.4) P5.2@1584.53,-1158.94 ; P5.2@1591.71,-1162.46 ccw(c1624.7,-1178.61) 1598.73,-1204.57 cw(c1624.7,-1178.61) P5.2@1591.71,-1162.46
AX: A.1 AH.3 AL.2 C7.2 C25.2 P1.6 P5.1 R1.2 R32.2 | length 5933.1
  Top Layer w10: P1.6@3550.22,-2259.28 P1.6@3550.22,-2244.09
  Top Layer w20: C7.2@1003.98,-766.09 1003.98,-705.19 AH.3@1051.01,-658.16 ; A.1@1224.31,-723.16 1244.1,-742.95 1244.1,-769.5 ccw(c1259.1,-769.5) 1259.1,-784.5 1349.1,-784.5 cw(c1349.1,-799.5) 1364.1,-799.5 1364.1,-819.5 cw(c1349.1,-819.5) 1349.1,-834.5 1139.1,-834.5 ccw(c1139.1,-849.5) 1124.1,-849.5 1124.1,-869.5 ccw(c1139.1,-869.5) 1139.1,-884.5 1349.1,-884.5 cw(c1349.1,-899.5) 1364.1,-899.5 1364.1,-919.5 cw(c1349.1,-919.5) 1349.1,-934.5 1139.1,-934.5 ccw(c1139.1,-949.5) 1124.1,-949.5 1124.1,-969.5 ccw(c1139.1,-969.5) 1139.1,-984.5 1229.1,-984.5 cw(c1229.1,-999.5) C25.2@1244.09,-999.32 ; v2(1521.85,-1610.9) 1521.84,-1331.55 R1.2@1564.85,-1288.54 1467.29,-1190.99 1467.29,-1137.04 1329.76,-999.5 C25.2@1244.1,-999.5 ; AL.2@1710.62,-454.72 1710.62,-472.22 1760.2,-521.8 R32.2@1857.9,-521.8 ; C25.2@1244.1,-999.5 ccw(c1229.1,-999.5) C25.2@1244.09,-999.32 ; C25.2@1244.1,-999.5 1244.1,-1009.5 C25.2@1240.79,-992.65 1237.41,-999.32 C25.2@1244.09,-999.32 ; 1467.29,-1191.01 ccw(c1433.94,-1191.01) 1455.92,-1165.93 cw(c1433.94,-1191.01) 1467.29,-1191.01 ; 1467.29,-1191.01 cw(c1495.91,-1191.01) 1479.79,-1167.37 ccw(c1495.91,-1191.01) 1467.29,-1191.01 ; C7.2@997.6,-760.73 ccw(c982.19,-745.32) 1003.98,-745.32 cw(c982.19,-745.32) C7.2@997.6,-760.73 ; 1013.74,-695.43 cw(c1042.93,-724.62) 1052.23,-684.4 ccw(c1042.93,-724.62) 1013.74,-695.43 ; AH.3@1039.25,-669.93 cw(c1052.51,-683.19) 1056.73,-664.91 ccw(c1052.51,-683.19) AH.3@1039.25,-669.93 ; 1179.15,-984.5 cw(c1179.15,-1052.32) 1227.1,-1004.37 ccw(c1179.15,-1052.32) 1179.15,-984.5 ; A.1@1213.41,-733.64 cw(c1205.08,-771.76) 1244.1,-771.76 ccw(c1205.08,-771.76) A.1@1213.41,-733.64 ; A.1@1217.68,-714.1 cw(c1210.51,-746.91) 1244.1,-746.91 ccw(c1210.51,-746.91) A.1@1217.68,-714.1 ; 1244.1,-759.21 cw(c1299.72,-759.21) 1260.39,-719.87 ccw(c1299.72,-759.21) 1244.1,-759.21 ; C25.2@1254.48,-980.93 ccw(c1299.33,-936.08) 1299.33,-999.5 cw(c1299.33,-936.08) C25.2@1254.48,-980.93 ; 1426.46,-1096.21 cw(c1371.43,-1151.24) 1449.26,-1151.24 ccw(c1371.43,-1151.24) 1426.46,-1096.21 ; 1539.25,-1314.15 cw(c1564.85,-1339.76) 1564.85,-1303.54 ccw(c1564.85,-1339.76) 1539.25,-1314.15 ; 1539.25,-1262.94 ccw(c1564.85,-1237.33) 1564.85,-1273.54 cw(c1564.85,-1237.33) 1539.25,-1262.94 ; R1.2@1547.32,-1306.07 ccw(c1533.14,-1291.89) 1553.2,-1291.89 cw(c1533.14,-1291.89) R1.2@1547.32,-1306.07 ; R1.2@1547.32,-1271.02 cw(c1533.14,-1285.2) 1553.2,-1285.2 ccw(c1533.14,-1285.2) R1.2@1547.32,-1271.02 ; 1820.45,-521.8 ccw(c1820.45,-472.36) 1855.41,-507.32 cw(c1820.45,-472.36) 1820.45,-521.8
  Bottom Layer w20: v2@1521.72,-1610.89 1770.59,-1610.89 2416.52,-2256.82 P1.6@3542.25,-2256.82 ; 3495.11,-2256.82 ccw(c3495.11,-2209.67) 3528.44,-2243.01 cw(c3495.11,-2209.67) 3495.11,-2256.82 ; 3495.11,-2256.82 cw(c3495.11,-2303.96) 3528.44,-2270.62 ccw(c3495.11,-2303.96) 3495.11,-2256.82
  other v3: 1191.23,-604.93 1429.89,-603.39 1322.11,-598.78 1435.28,-511.01 1323.65,-497.92 1193.54,-494.07 1528.43,-419.4 1327.5,-388.6 1198.16,-386.29 1438.36,-382.44
BI: BL.3 P6.3 R16.2 | length 1855.3
  Top Layer w10: P6.3@2717.75,-1146.43 2979.37,-1146.43 3032.42,-1093.38 3032.42,-789.64 3022.06,-779.28 ; R16.2@2928.85,-779.28 3022.06,-779.28 ; 3022.06,-779.28 cw(c3022.06,-698.28) 2963.36,-754.1 ccw(c3022.06,-698.28) 3022.06,-779.28 ; P6.3@2728.02,-1161.51 cw(c2764.44,-1197.92) 2764.44,-1146.43 ccw(c2764.44,-1197.92) P6.3@2728.02,-1161.51 ; P6.3@2735.09,-1168.58 cw(c2788.58,-1222.06) 2788.58,-1146.43 ccw(c2788.58,-1222.06) P6.3@2735.09,-1168.58 ; P6.3@2735.09,-1133.89 ccw(c2765.35,-1103.64) 2765.35,-1146.43 cw(c2765.35,-1103.64) P6.3@2735.09,-1133.89 ; R16.2@2948.86,-767.88 ccw(c2975.44,-742.61) 2975.44,-779.28 cw(c2975.44,-742.61) R16.2@2948.86,-767.88 ; R16.2@2956.11,-760.99 ccw(c2998.75,-720.44) 2998.75,-779.28 cw(c2998.75,-720.44) R16.2@2956.11,-760.99 ; R16.2@2962.93,-788.35 cw(c2984.8,-810.22) 2984.8,-779.28 ccw(c2984.8,-810.22) R16.2@2962.93,-788.35
  Top Layer w20: BL.3@2858.32,-639.99 2878.07,-639.99 2918.43,-680.35 R16.2@2918.43,-785.12 ; BL.3@2843.51,-638.78 cw(c2858.37,-672.8) 2884.62,-646.55 ccw(c2858.37,-672.8) BL.3@2843.51,-638.78 ; BL.3@2851.52,-657.11 cw(c2870.98,-701.65) 2905.35,-667.28 ccw(c2870.98,-701.65) BL.3@2851.52,-657.11 ; R16.2@2896.34,-757.19 ccw(c2843.02,-703.87) 2918.43,-703.87 cw(c2843.02,-703.87) R16.2@2896.34,-757.19
BP: P1.15 P6.2 | length 1462.3
  Top Layer w10: P6.2@2617.75,-1151.24 2617.75,-1192.54 ; P1.15@3642.25,-1756.82 3611.25,-1725.82 3611.25,-1612.58 3559.99,-1561.32 3154.18,-1561.32 2799.34,-1206.49 2631.7,-1206.49 2617.75,-1192.54 ; 2617.75,-1192.54 ccw(c2595.25,-1192.54) 2606.01,-1172.78 cw(c2595.25,-1192.54) 2617.75,-1192.54 ; 2617.75,-1192.54 cw(c2640.26,-1192.54) 2629.49,-1172.78 ccw(c2640.26,-1192.54) 2617.75,-1192.54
